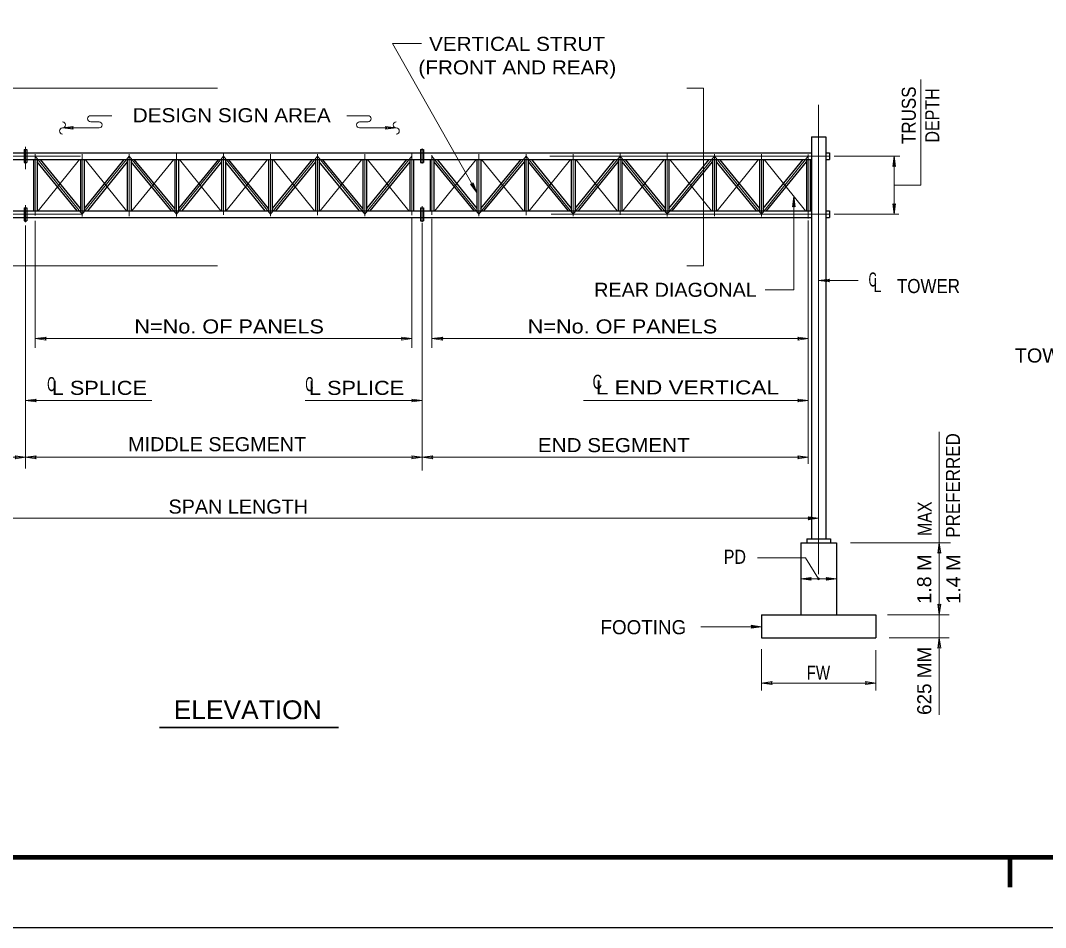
# Model space of a CAD drawing. Extents: x 312601.858 to 312602.699, y 144420.11 to 144420.704.
# Drawn here: x 312602.0675 to 312602.2859, y 144420.1096 to 144420.3029 of the extents above; entities that cross this region are included whole.
import ezdxf
from ezdxf.enums import TextEntityAlignment as Align

# ---------------------------------------------------------------- set-up
doc = ezdxf.new("R2010")
doc.units = 0
doc.header["$LTSCALE"] = 0.0012
doc.linetypes.add('DOT_DASHED', pattern=[7.7, 5, -1.2, 0.3, -1.2])
doc.linetypes.add('LONG_DASHED', pattern=[7.5, 6, -1.5])
for name, color, linetype, lineweight in [('1', 7, 'Continuous', 25), ('2', 7, 'Continuous', 13), ('39', 7, 'Continuous', 13)]:
    doc.layers.add(name, color=color, linetype=linetype, lineweight=lineweight)

msp = doc.modelspace()

# ---------------------------------------------------------------- hatches: boundary and pattern name
at = {"layer": '1'}
msp.add_hatch(color=256, dxfattribs=at).paths.add_polyline_path([(312602.2378, 144420.1839, 1), (312602.2374, 144420.1839, 1)])
at = {"layer": '39'}
for points in [[(312602.2537, 144420.272), (312602.2534, 144420.2718), (312602.2537, 144420.274), (312602.254, 144420.2718)], [(312602.1638, 144420.268), (312602.164, 144420.2683), (312602.1648, 144420.2662), (312602.1634, 144420.268)], [(312602.2323, 144420.2634), (312602.232, 144420.2632), (312602.2323, 144420.2654), (312602.2326, 144420.2632)], [(312602.2537, 144420.2636), (312602.254, 144420.2638), (312602.2537, 144420.2616), (312602.2534, 144420.2638)], [(312602.2356, 144420.1968), (312602.2354, 144420.1971), (312602.2376, 144420.1968), (312602.2354, 144420.1965)], [(312602.2358, 144420.1839), (312602.236, 144420.1836), (312602.2338, 144420.1839), (312602.236, 144420.1842)], [(312602.2394, 144420.1839), (312602.2392, 144420.1842), (312602.2414, 144420.1839), (312602.2392, 144420.1836)], [(312602.2234, 144420.1737), (312602.2232, 144420.174), (312602.2254, 144420.1737), (312602.2232, 144420.1734)], [(312602.2234, 144420.1737), (312602.2232, 144420.174), (312602.2254, 144420.1737), (312602.2232, 144420.1734)]]:
    msp.add_hatch(color=256, dxfattribs=at).paths.add_polyline_path(points)

# ---------------------------------------------------------------- linework, layer by layer
at = {"layer": '1', "lineweight": 13}
for p, q in [((312602.1468, 144420.298), (312602.153, 144420.298)), ((312602.1648, 144420.2662), (312602.1468, 144420.298)), ((312602.2594, 144420.2903), (312602.2594, 144420.2678)), ((312602.0825, 144420.2826), (312602.087, 144420.2826)), ((312602.1416, 144420.2826), (312602.1371, 144420.2826)), ((312602.0825, 144420.2813), (312602.0843, 144420.2813)), ((312602.1416, 144420.2813), (312602.1398, 144420.2813)), ((312602.0765, 144420.28), (312602.0843, 144420.28)), ((312602.1476, 144420.28), (312602.1398, 144420.28)), ((312602.2391, 144420.2747), (312602.2399, 144420.2747)), ((312602.2409, 144420.274), (312602.2549, 144420.274)), ((312602.2537, 144420.274), (312602.2537, 144420.2616)), ((312602.2391, 144420.2733), (312602.2399, 144420.2733)), ((312602.2323, 144420.2455), (312602.2323, 144420.2654)), ((312602.1509, 144420.2607), (312602.1509, 144420.2331)), ((312602.1552, 144420.2606), (312602.1552, 144420.2331)), ((312602.2409, 144420.2616), (312602.2547, 144420.2616)), ((312602.0686, 144420.2592), (312602.0686, 144420.2074)), ((312602.0707, 144420.2602), (312602.0707, 144420.2331)), ((312602.1531, 144420.2598), (312602.1531, 144420.207)), ((312602.2376, 144420.2475), (312602.246, 144420.2475)), ((312602.2262, 144420.2455), (312602.2323, 144420.2455)), ((312602.0707, 144420.2351), (312602.1509, 144420.2351)), ((312602.1552, 144420.2351), (312602.2354, 144420.2351)), ((312602.0686, 144420.2219), (312602.0955, 144420.2219)), ((312602.1282, 144420.2219), (312602.1531, 144420.2219)), ((312602.1875, 144420.2219), (312602.2354, 144420.2219)), ((312601.984, 144420.1968), (312602.2376, 144420.1968)), ((312602.2444, 144420.1916), (312602.2657, 144420.1916)), ((312602.2246, 144420.1884), (312602.2348, 144420.1884)), ((312602.2348, 144420.1884), (312602.2376, 144420.1839)), ((312602.2338, 144420.1839), (312602.2414, 144420.1839)), ((312602.2523, 144420.1762), (312602.2654, 144420.1762)), ((312602.2633, 144420.1762), (312602.2633, 144420.1713)), ((312602.2125, 144420.1737), (312602.2254, 144420.1737)), ((312602.2526, 144420.1713), (312602.2654, 144420.1713)), ((312602.2633, 144420.1713), (312602.2633, 144420.1549)), ((312602.2254, 144420.1689), (312602.2254, 144420.1601)), ((312602.2498, 144420.1687), (312602.2498, 144420.1601)), ((312602.2254, 144420.1617), (312602.2498, 144420.1617))]:
    msp.add_line(p, q, dxfattribs=at)
at = {"layer": '1', "linetype": 'LONG_DASHED', "lineweight": 13}
for p, q in [((312602.0095, 144420.2885), (312602.2131, 144420.2885)), ((312602.2131, 144420.2885), (312602.2131, 144420.2506)), ((312602.0801, 144420.2733), (312602.0713, 144420.2623)), ((312602.0901, 144420.2623), (312602.0813, 144420.2733)), ((312602.1002, 144420.2733), (312602.0913, 144420.2623)), ((312602.1102, 144420.2623), (312602.1014, 144420.2733)), ((312602.1202, 144420.2733), (312602.1114, 144420.2623)), ((312602.1302, 144420.2623), (312602.1214, 144420.2733)), ((312602.1403, 144420.2733), (312602.1314, 144420.2623)), ((312602.1503, 144420.2623), (312602.1415, 144420.2733)), ((312602.1558, 144420.2623), (312602.1646, 144420.2733)), ((312602.1658, 144420.2733), (312602.1747, 144420.2623)), ((312602.1759, 144420.2623), (312602.1847, 144420.2733)), ((312602.1859, 144420.2733), (312602.1947, 144420.2623)), ((312602.1959, 144420.2623), (312602.2047, 144420.2733)), ((312602.2059, 144420.2733), (312602.2148, 144420.2623)), ((312602.216, 144420.2623), (312602.2248, 144420.2733)), ((312602.226, 144420.2733), (312602.2348, 144420.2623)), ((312602.0095, 144420.2506), (312602.2131, 144420.2506))]:
    msp.add_line(p, q, dxfattribs=at)
at = {"layer": '1', "linetype": 'DOT_DASHED', "lineweight": 13}
for p, q in [((312602.2376, 144420.2849), (312602.2376, 144420.1686)), ((312602.0686, 144420.276), (312602.0686, 144420.2712)), ((312601.9803, 144420.274), (312602.2399, 144420.274)), ((312602.0707, 144420.2744), (312602.0707, 144420.2613)), ((312602.0807, 144420.2744), (312602.0807, 144420.2611)), ((312602.0907, 144420.2744), (312602.0907, 144420.2612)), ((312602.1008, 144420.2745), (312602.1008, 144420.2611)), ((312602.1108, 144420.2745), (312602.1108, 144420.2615)), ((312602.1208, 144420.2744), (312602.1208, 144420.2612)), ((312602.1308, 144420.2744), (312602.1308, 144420.2614)), ((312602.1409, 144420.2744), (312602.1409, 144420.2612)), ((312602.1509, 144420.2745), (312602.1509, 144420.2614)), ((312602.1531, 144420.2756), (312602.1531, 144420.2724)), ((312602.1552, 144420.2742), (312602.1552, 144420.2615)), ((312602.1652, 144420.2744), (312602.1652, 144420.2612)), ((312602.1753, 144420.2744), (312602.1753, 144420.2614)), ((312602.1853, 144420.2744), (312602.1853, 144420.2612)), ((312602.1953, 144420.2745), (312602.1953, 144420.2615)), ((312602.2053, 144420.2745), (312602.2053, 144420.2611)), ((312602.2154, 144420.2744), (312602.2154, 144420.2612)), ((312602.2254, 144420.2744), (312602.2254, 144420.2611)), ((312602.2254, 144420.2616), (312602.2354, 144420.274)), ((312602.2354, 144420.2743), (312602.2354, 144420.2607)), ((312602.0686, 144420.2635), (312602.0686, 144420.2599)), ((312602.1531, 144420.2633), (312602.1531, 144420.26)), ((312601.9806, 144420.2616), (312602.2398, 144420.2616))]:
    msp.add_line(p, q, dxfattribs=at)
at = {"layer": '1'}
for p, q in [((312602.2361, 144420.2781), (312602.2391, 144420.2781)), ((312602.2361, 144420.2781), (312602.2361, 144420.1924)), ((312602.2391, 144420.2781), (312602.2391, 144420.1924)), ((312601.9855, 144420.2747), (312602.2361, 144420.2747)), ((312602.0683, 144420.2754), (312602.0683, 144420.2726)), ((312602.0683, 144420.2754), (312602.0689, 144420.2754)), ((312602.0689, 144420.2754), (312602.0689, 144420.2726)), ((312602.1528, 144420.2754), (312602.1528, 144420.2726)), ((312602.1528, 144420.2754), (312602.1534, 144420.2754)), ((312602.1534, 144420.2754), (312602.1534, 144420.2726)), ((312602.2391, 144420.2747), (312602.2399, 144420.2747)), ((312602.2399, 144420.2747), (312602.2399, 144420.2733)), ((312601.9855, 144420.2733), (312602.2361, 144420.2733)), ((312602.0683, 144420.2726), (312602.0689, 144420.2726)), ((312602.0703, 144420.2733), (312602.0703, 144420.2623)), ((312602.0711, 144420.2733), (312602.0711, 144420.2623)), ((312602.0796, 144420.2623), (312602.0711, 144420.2728)), ((312602.0803, 144420.2628), (312602.0718, 144420.2733)), ((312602.0803, 144420.2733), (312602.0803, 144420.2623)), ((312602.0811, 144420.2733), (312602.0811, 144420.2623)), ((312602.0896, 144420.2733), (312602.0811, 144420.2628)), ((312602.0903, 144420.2728), (312602.0818, 144420.2623)), ((312602.0903, 144420.2733), (312602.0903, 144420.2623)), ((312602.0911, 144420.2733), (312602.0911, 144420.2623)), ((312602.0997, 144420.2623), (312602.0911, 144420.2728)), ((312602.1004, 144420.2628), (312602.0918, 144420.2733)), ((312602.1004, 144420.2733), (312602.1004, 144420.2623)), ((312602.1012, 144420.2733), (312602.1012, 144420.2623)), ((312602.1097, 144420.2733), (312602.1012, 144420.2628)), ((312602.1104, 144420.2728), (312602.1019, 144420.2623)), ((312602.1104, 144420.2733), (312602.1104, 144420.2623)), ((312602.1112, 144420.2733), (312602.1112, 144420.2623)), ((312602.1197, 144420.2623), (312602.1112, 144420.2728)), ((312602.1204, 144420.2628), (312602.1119, 144420.2733)), ((312602.1204, 144420.2733), (312602.1204, 144420.2623)), ((312602.1212, 144420.2733), (312602.1212, 144420.2623)), ((312602.1297, 144420.2733), (312602.1212, 144420.2628)), ((312602.1304, 144420.2728), (312602.1219, 144420.2623)), ((312602.1304, 144420.2733), (312602.1304, 144420.2623)), ((312602.1312, 144420.2733), (312602.1312, 144420.2623)), ((312602.1398, 144420.2623), (312602.1312, 144420.2728)), ((312602.1405, 144420.2628), (312602.1319, 144420.2733)), ((312602.1405, 144420.2733), (312602.1405, 144420.2623)), ((312602.1413, 144420.2733), (312602.1413, 144420.2623)), ((312602.1498, 144420.2733), (312602.1413, 144420.2628)), ((312602.1505, 144420.2728), (312602.142, 144420.2623)), ((312602.1505, 144420.2733), (312602.1505, 144420.2623)), ((312602.1513, 144420.2733), (312602.1513, 144420.2623)), ((312602.1528, 144420.2726), (312602.1534, 144420.2726)), ((312602.1548, 144420.2733), (312602.1548, 144420.2623)), ((312602.1556, 144420.2733), (312602.1556, 144420.2623)), ((312602.1556, 144420.2728), (312602.1641, 144420.2623)), ((312602.1563, 144420.2733), (312602.1648, 144420.2628)), ((312602.1648, 144420.2733), (312602.1648, 144420.2623)), ((312602.1656, 144420.2733), (312602.1656, 144420.2623)), ((312602.1656, 144420.2628), (312602.1742, 144420.2733)), ((312602.1663, 144420.2623), (312602.1749, 144420.2728)), ((312602.1749, 144420.2733), (312602.1749, 144420.2623)), ((312602.1757, 144420.2733), (312602.1757, 144420.2623)), ((312602.1757, 144420.2728), (312602.1842, 144420.2623)), ((312602.1764, 144420.2733), (312602.1849, 144420.2628)), ((312602.1849, 144420.2733), (312602.1849, 144420.2623)), ((312602.1857, 144420.2733), (312602.1857, 144420.2623)), ((312602.1857, 144420.2628), (312602.1942, 144420.2733)), ((312602.1864, 144420.2623), (312602.1949, 144420.2728)), ((312602.1949, 144420.2733), (312602.1949, 144420.2623)), ((312602.1957, 144420.2733), (312602.1957, 144420.2623)), ((312602.1957, 144420.2728), (312602.2042, 144420.2623)), ((312602.1964, 144420.2733), (312602.2049, 144420.2628)), ((312602.2049, 144420.2733), (312602.2049, 144420.2623)), ((312602.2057, 144420.2733), (312602.2057, 144420.2623)), ((312602.2057, 144420.2628), (312602.2143, 144420.2733)), ((312602.2064, 144420.2623), (312602.215, 144420.2728)), ((312602.215, 144420.2733), (312602.215, 144420.2623)), ((312602.2158, 144420.2733), (312602.2158, 144420.2623)), ((312602.2158, 144420.2728), (312602.2243, 144420.2623)), ((312602.2165, 144420.2733), (312602.225, 144420.2628)), ((312602.225, 144420.2733), (312602.225, 144420.2623)), ((312602.2258, 144420.2628), (312602.2343, 144420.2733)), ((312602.2258, 144420.2733), (312602.2258, 144420.2623)), ((312602.2265, 144420.2623), (312602.235, 144420.2728)), ((312602.235, 144420.2733), (312602.235, 144420.2623)), ((312602.2358, 144420.2733), (312602.2358, 144420.2623)), ((312602.2391, 144420.2733), (312602.2399, 144420.2733)), ((312602.0683, 144420.263), (312602.0683, 144420.2602)), ((312602.0683, 144420.263), (312602.0689, 144420.263)), ((312602.0689, 144420.263), (312602.0689, 144420.2602)), ((312602.1528, 144420.263), (312602.1528, 144420.2602)), ((312602.1528, 144420.263), (312602.1534, 144420.263)), ((312602.1534, 144420.263), (312602.1534, 144420.2602)), ((312601.9855, 144420.2623), (312602.2361, 144420.2623)), ((312601.9855, 144420.2609), (312602.2361, 144420.2609)), ((312602.2391, 144420.2623), (312602.2399, 144420.2623)), ((312602.2391, 144420.2609), (312602.2399, 144420.2609)), ((312602.2399, 144420.2623), (312602.2399, 144420.2609)), ((312602.0683, 144420.2602), (312602.0689, 144420.2602)), ((312602.1528, 144420.2602), (312602.1534, 144420.2602)), ((312602.2338, 144420.1916), (312602.2414, 144420.1916)), ((312602.2338, 144420.1916), (312602.2338, 144420.1762)), ((312602.2351, 144420.1924), (312602.2351, 144420.1916)), ((312602.2351, 144420.1924), (312602.2401, 144420.1924)), ((312602.2401, 144420.1924), (312602.2401, 144420.1916)), ((312602.2414, 144420.1916), (312602.2414, 144420.1762)), ((312602.2254, 144420.1762), (312602.2254, 144420.1713)), ((312602.2254, 144420.1762), (312602.2498, 144420.1762)), ((312602.2498, 144420.1762), (312602.2498, 144420.1713)), ((312602.2254, 144420.1713), (312602.2498, 144420.1713))]:
    msp.add_line(p, q, dxfattribs=at)
at = {"layer": '1', "lineweight": 13}
for points in [[(312602.0788, 144420.2797), (312602.0765, 144420.28), (312602.0788, 144420.2803), (312602.0785, 144420.28)], [(312602.1453, 144420.2797), (312602.1476, 144420.28), (312602.1453, 144420.2803), (312602.1456, 144420.28)], [(312602.2399, 144420.2472), (312602.2376, 144420.2475), (312602.2399, 144420.2478), (312602.2396, 144420.2475)], [(312602.073, 144420.2348), (312602.0707, 144420.2351), (312602.073, 144420.2354), (312602.0727, 144420.2351)], [(312602.1487, 144420.2354), (312602.1509, 144420.2351), (312602.1487, 144420.2348), (312602.1489, 144420.2351)], [(312602.1575, 144420.2348), (312602.1552, 144420.2351), (312602.1575, 144420.2354), (312602.1572, 144420.2351)], [(312602.2332, 144420.2354), (312602.2354, 144420.2351), (312602.2332, 144420.2348), (312602.2334, 144420.2351)], [(312602.0709, 144420.2216), (312602.0686, 144420.2219), (312602.0709, 144420.2222), (312602.0706, 144420.2219)], [(312602.1509, 144420.2222), (312602.1531, 144420.2219), (312602.1509, 144420.2216), (312602.1511, 144420.2219)], [(312602.2332, 144420.2222), (312602.2354, 144420.2219), (312602.2332, 144420.2216), (312602.2334, 144420.2219)], [(312602.0664, 144420.2101), (312602.0686, 144420.2098), (312602.0664, 144420.2095), (312602.0666, 144420.2098)], [(312602.0709, 144420.2095), (312602.0686, 144420.2098), (312602.0709, 144420.2101), (312602.0706, 144420.2098)], [(312602.1509, 144420.2101), (312602.1531, 144420.2098), (312602.1509, 144420.2095), (312602.1511, 144420.2098)], [(312602.1554, 144420.2095), (312602.1531, 144420.2098), (312602.1554, 144420.2101), (312602.1551, 144420.2098)], [(312602.2332, 144420.2101), (312602.2354, 144420.2098), (312602.2332, 144420.2095), (312602.2334, 144420.2098)], [(312602.263, 144420.1894), (312602.2633, 144420.1916), (312602.2636, 144420.1894), (312602.2633, 144420.1896)], [(312602.2636, 144420.1785), (312602.2633, 144420.1762), (312602.263, 144420.1785), (312602.2633, 144420.1782)], [(312602.263, 144420.1691), (312602.2633, 144420.1713), (312602.2636, 144420.1691), (312602.2633, 144420.1693)], [(312602.2277, 144420.1614), (312602.2254, 144420.1617), (312602.2277, 144420.162), (312602.2274, 144420.1617)], [(312602.2476, 144420.162), (312602.2498, 144420.1617), (312602.2476, 144420.1614), (312602.2478, 144420.1617)]]:
    msp.add_lwpolyline(points, close=True, dxfattribs=at)
at = {"layer": '1', "linetype": 'DOT_DASHED', "lineweight": 13}
for points in [[(312602.1509, 144420.274), (312602.1409, 144420.2616), (312602.1308, 144420.274), (312602.1208, 144420.2616), (312602.1108, 144420.274), (312602.1008, 144420.2616), (312602.0907, 144420.274), (312602.0807, 144420.2616), (312602.0707, 144420.274)], [(312602.1552, 144420.274), (312602.1652, 144420.2616), (312602.1753, 144420.274), (312602.1853, 144420.2616), (312602.1953, 144420.274), (312602.2053, 144420.2616), (312602.2154, 144420.274), (312602.2254, 144420.2616)]]:
    msp.add_lwpolyline(points, dxfattribs=at)
at = {"layer": '1', "lineweight": 13}
msp.add_lwpolyline([(312602.2633, 144420.2152), (312602.2633, 144420.1916), (312602.2633, 144420.1762)], dxfattribs=at)
msp.add_circle((312602.2376, 144420.1839), 0.0002, dxfattribs=at)
for centre, start, end in [((312602.0825, 144420.28195), 90, 270), ((312602.1416, 144420.28195), 270, 90), ((312602.0765, 144420.28065), 270, 90), ((312602.0843, 144420.28065), 270, 90), ((312602.1398, 144420.28065), 90, 270), ((312602.1476, 144420.28065), 90, 270), ((312602.0765, 144420.27935), 90, 270), ((312602.1476, 144420.27935), 270, 90)]:
    msp.add_arc(centre, 0.00065, start, end, dxfattribs=at)
for points in [[(312602.2354, 144420.2603), (312602.2354, 144420.2084)], [(312601.9862, 144420.2098), (312602.2354, 144420.2098)]]:
    msp.add_open_spline(points, degree=1, dxfattribs=at)
at = {"layer": '2'}
msp.add_line((312602.2594, 144420.2678), (312602.2537, 144420.2678), dxfattribs=at)
at = {"layer": '2', "lineweight": 35}
msp.add_line((312602.0972, 144420.1522), (312602.1353, 144420.1522), dxfattribs=at)
at = {"layer": '39', "lineweight": 158}
msp.add_line((312602.2784, 144420.1182), (312602.2784, 144420.1246), dxfattribs=at)
at = {"layer": '39', "lineweight": 25}
msp.add_lwpolyline([(312601.8579, 144420.1096), (312602.6989, 144420.1096), (312602.6989, 144420.7036)], dxfattribs=at)
at = {"layer": '39', "lineweight": 158}
msp.add_lwpolyline([(312601.9089, 144420.1246), (312602.6839, 144420.1246), (312602.6839, 144420.6646)], dxfattribs=at)
at = {"layer": '39'}
for points in [[(312602.2537, 144420.272), (312602.2534, 144420.2718), (312602.2537, 144420.274), (312602.254, 144420.2718)], [(312602.1638, 144420.268), (312602.164, 144420.2683), (312602.1648, 144420.2662), (312602.1634, 144420.268)], [(312602.2323, 144420.2634), (312602.232, 144420.2632), (312602.2323, 144420.2654), (312602.2326, 144420.2632)], [(312602.2537, 144420.2636), (312602.254, 144420.2638), (312602.2537, 144420.2616), (312602.2534, 144420.2638)], [(312602.2356, 144420.1968), (312602.2354, 144420.1971), (312602.2376, 144420.1968), (312602.2354, 144420.1965)], [(312602.2358, 144420.1839), (312602.236, 144420.1836), (312602.2338, 144420.1839), (312602.236, 144420.1842)], [(312602.2394, 144420.1839), (312602.2392, 144420.1842), (312602.2414, 144420.1839), (312602.2392, 144420.1836)], [(312602.2234, 144420.1737), (312602.2232, 144420.174), (312602.2254, 144420.1737), (312602.2232, 144420.1734)], [(312602.2234, 144420.1737), (312602.2232, 144420.174), (312602.2254, 144420.1737), (312602.2232, 144420.1734)]]:
    msp.add_lwpolyline(points, close=True, dxfattribs=at)

# ---------------------------------------------------------------- texts
at = {"layer": '1'}
for s, width, p in [('TOWER', 0.9, (312602.261, 144420.2448)), ('C', 0.7, (312602.19045, 144420.2244)), ('L END VERTICAL ', 1.2, (312602.2103, 144420.2232)), ('MIDDLE SEGMENT', 1.05, (312602.10945, 144420.2111)), ('END SEGMENT', 1.1, (312602.19395, 144420.2109)), ('FW', 0.8, (312602.23755, 144420.1624))]:
    msp.add_text(s, height=0.003, dxfattribs=dict(at, width=width)).set_placement(p, align=Align.CENTER)
at = {"layer": '1', "width": 1.05}
msp.add_text('TOWER DIAGONAL', height=0.003, dxfattribs=at).set_placement((312602.2794, 144420.23))
at = {"layer": '1'}
for s, width, p in [('PREFERRED', 0.9, (312602.2677, 144420.2038)), ('MAX', 0.85, (312602.2617, 144420.1967)), ('1.8 M', 1.05, (312602.2616, 144420.18385)), ('1.4 M', 1.05, (312602.2678, 144420.18385))]:
    msp.add_text(s, height=0.003, rotation=90, dxfattribs=dict(at, width=width)).set_placement(p, align=Align.CENTER)
msp.add_text('625 MM', height=0.003, rotation=90, dxfattribs=at).set_placement((312602.2616, 144420.16215), align=Align.CENTER)
at = {"layer": '2'}
for s, height, width, p in [('VERTICAL STRUT', 0.003, 1.1, (312602.17335, 144420.2964)), ('(FRONT AND REAR)', 0.003, 1.1, (312602.1734, 144420.2914)), ('DESIGN SIGN AREA', 0.003, 1.1, (312602.11255, 144420.2812)), ('C', 0.003, 0.6, (312602.2491, 144420.2462)), ('L', 0.003, 0.75, (312602.25015, 144420.245)), ('REAR DIAGONAL', 0.003, 1.05, (312602.2071, 144420.244)), ('N=No. OF PANELS', 0.003, 1.15, (312602.112, 144420.2362)), ('N=No. OF PANELS', 0.003, 1.15, (312602.1958, 144420.2362)), ('C', 0.003, 0.6, (312602.0741, 144420.2239)), ('L SPLICE', 0.003, 1.15, (312602.08435, 144420.2231)), ('C', 0.003, 0.6, (312602.1291, 144420.2239)), ('L SPLICE', 0.003, 1.15, (312602.13915, 144420.2231)), ('SPAN LENGTH', 0.003, 1.05, (312602.11395, 144420.1978)), ('PD', 0.003, 0.85, (312602.21975, 144420.1871)), ('ELEVATION', 0.004, 1.05, (312602.11595, 144420.154))]:
    msp.add_text(s, height=height, dxfattribs=dict(at, width=width)).set_placement(p, align=Align.CENTER)
for s, width, p in [('TRUSS', 0.9, (312602.2583, 144420.2827)), ('DEPTH', 0.85, (312602.2633, 144420.28265))]:
    msp.add_text(s, height=0.003, rotation=90, dxfattribs=dict(at, width=width)).set_placement(p, align=Align.CENTER)
msp.add_text('FOOTING', height=0.003, dxfattribs=at).set_placement((312602.20025, 144420.1721), align=Align.CENTER)

doc.saveas('drawing.dxf')
